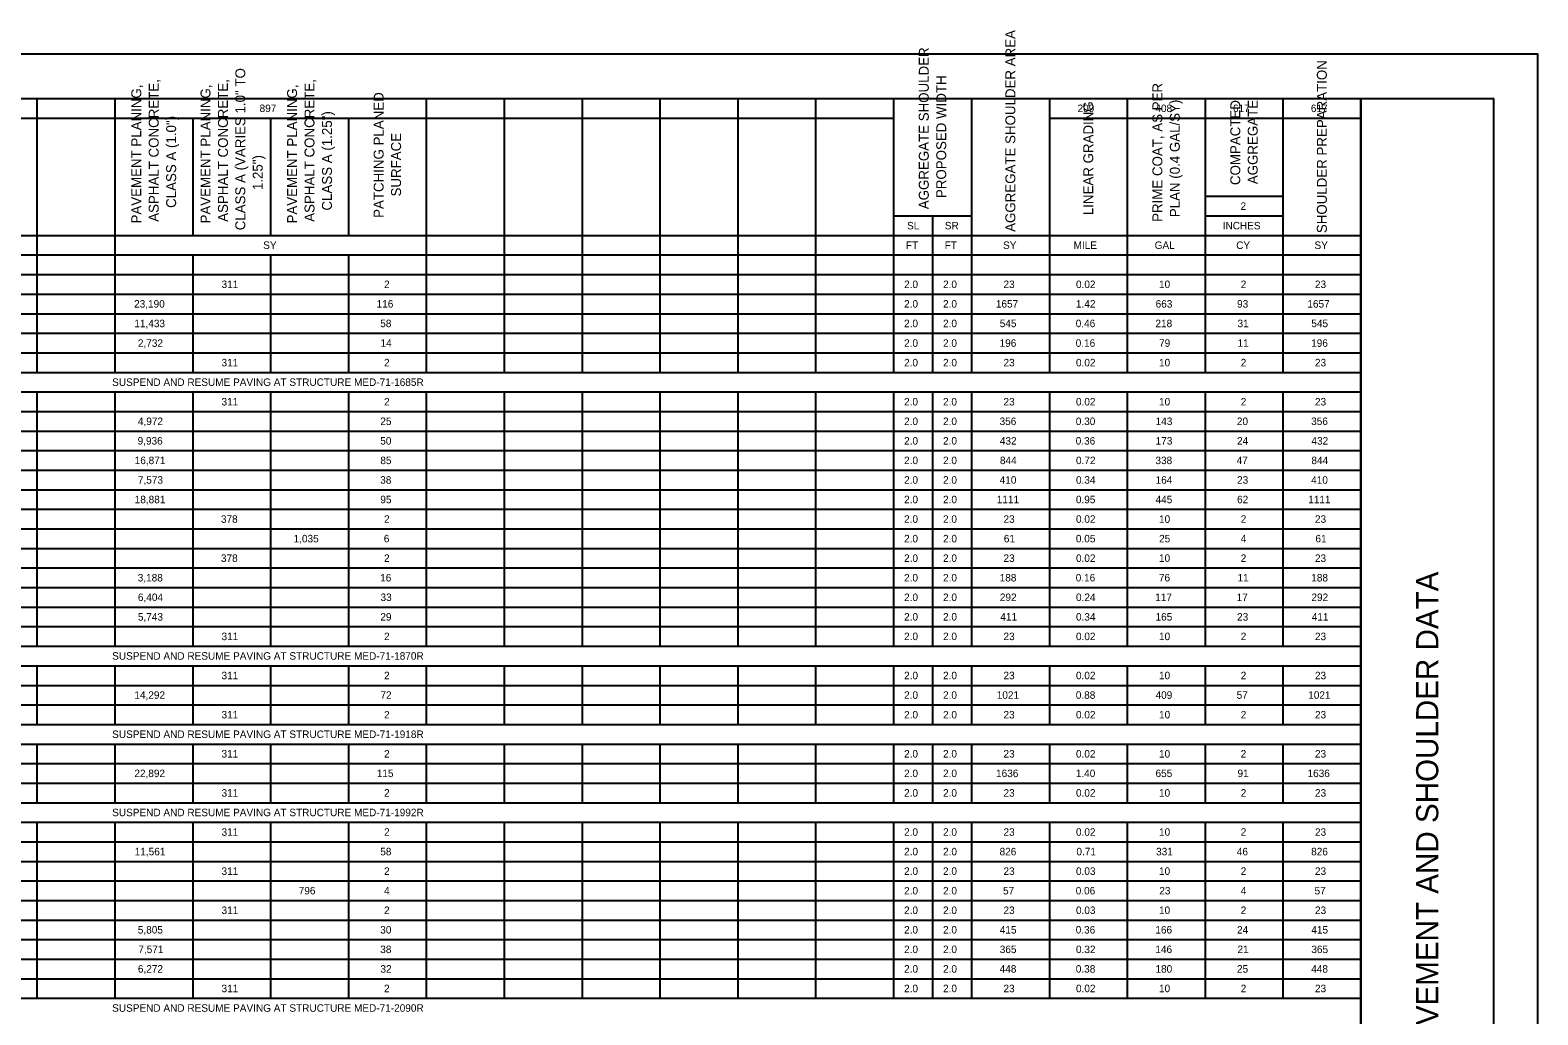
# Model space of a CAD drawing. Extents: x 0 to 34, y 0 to 22.3.
# Drawn here: x 16.97 to 34, y 11.14 to 22.27 of the extents above; entities that cross this region are included whole.
import ezdxf

# ---------------------------------------------------------------- set-up
doc = ezdxf.new("R2010")
doc.units = 0
for name, color, linetype in [('SH_Border', 7, 'Continuous'), ('SH_Cut_Line', 7, 'Continuous'), ('SH_Data', 7, 'Continuous'), ('SH_Text', 7, 'Continuous')]:
    doc.layers.add(name, color=color, linetype=linetype)

msp = doc.modelspace()

# ---------------------------------------------------------------- linework, layer by layer
at = {"layer": 'SH_Border'}
msp.add_line((32, 0.5), (32, 21.5), dxfattribs=at)
msp.add_lwpolyline([(1.5, 21.5), (33.5, 21.5), (33.5, 0.5), (1.5, 0.5)], close=True, dxfattribs=at)
at = {"layer": 'SH_Cut_Line'}
msp.add_lwpolyline([(0, 0), (34, 0), (34, 22), (0, 22)], close=True, dxfattribs=at)
at = {"layer": 'SH_Text'}
for p, q in [((1.5, 21.5), (32, 21.5)), ((17.043, 21.5), (17.043, 18.405)), ((17.923, 21.5), (17.923, 18.405)), ((21.442, 21.5), (21.442, 18.405)), ((22.322, 21.5), (22.322, 18.405)), ((23.202, 21.5), (23.202, 18.405)), ((24.082, 21.5), (24.082, 18.405)), ((24.962, 21.5), (24.962, 18.405)), ((25.841, 21.5), (25.841, 18.405)), ((26.721, 21.5), (26.721, 18.405)), ((27.601, 21.5), (27.601, 18.405)), ((28.481, 21.5), (28.481, 18.405)), ((29.361, 21.5), (29.361, 18.405)), ((30.24, 21.5), (30.24, 18.405)), ((31.12, 21.5), (31.12, 18.405)), ((32, 21.5), (32, 0.5)), ((10.885, 21.279), (26.721, 21.279)), ((18.803, 21.279), (18.803, 19.953)), ((19.683, 21.279), (19.683, 19.953)), ((20.562, 21.279), (20.562, 19.953)), ((28.481, 21.279), (32, 21.279)), ((30.24, 20.395), (31.12, 20.395)), ((26.721, 20.174), (27.601, 20.174)), ((27.161, 20.174), (27.161, 18.405)), ((30.24, 20.174), (31.12, 20.174)), ((10.005, 19.953), (32, 19.953)), ((1.5, 19.732), (32, 19.732)), ((18.803, 19.732), (18.803, 18.405)), ((19.683, 19.732), (19.683, 18.405)), ((20.562, 19.732), (20.562, 18.405)), ((1.5, 19.511), (32, 19.511)), ((1.5, 19.289), (32, 19.289)), ((1.5, 19.068), (32, 19.068)), ((1.5, 18.847), (32, 18.847)), ((1.5, 18.626), (32, 18.626)), ((1.5, 18.405), (32, 18.405)), ((1.5, 18.184), (32, 18.184)), ((17.043, 18.184), (17.043, 15.311)), ((17.923, 18.184), (17.923, 15.311)), ((18.803, 18.184), (18.803, 15.311)), ((19.683, 18.184), (19.683, 15.311)), ((20.562, 18.184), (20.562, 15.311)), ((21.442, 18.184), (21.442, 15.311)), ((22.322, 18.184), (22.322, 15.311)), ((23.202, 18.184), (23.202, 15.311)), ((24.082, 18.184), (24.082, 15.311)), ((24.962, 18.184), (24.962, 15.311)), ((25.841, 18.184), (25.841, 15.311)), ((26.721, 18.184), (26.721, 15.311)), ((27.161, 18.184), (27.161, 15.311)), ((27.601, 18.184), (27.601, 15.311)), ((28.481, 18.184), (28.481, 15.311)), ((29.361, 18.184), (29.361, 15.311)), ((30.24, 18.184), (30.24, 15.311)), ((31.12, 18.184), (31.12, 15.311)), ((1.5, 17.963), (32, 17.963)), ((1.5, 17.742), (32, 17.742)), ((1.5, 17.521), (32, 17.521)), ((1.5, 17.3), (32, 17.3)), ((1.5, 17.079), (32, 17.079)), ((1.5, 16.858), (32, 16.858)), ((1.5, 16.637), (32, 16.637)), ((1.5, 16.416), (32, 16.416)), ((1.5, 16.195), (32, 16.195)), ((1.5, 15.974), (32, 15.974)), ((1.5, 15.753), (32, 15.753)), ((1.5, 15.532), (32, 15.532)), ((1.5, 15.311), (32, 15.311)), ((1.5, 15.089), (32, 15.089)), ((17.043, 15.089), (17.043, 14.426)), ((17.923, 15.089), (17.923, 14.426)), ((18.803, 15.089), (18.803, 14.426)), ((19.683, 15.089), (19.683, 14.426)), ((20.562, 15.089), (20.562, 14.426)), ((21.442, 15.089), (21.442, 14.426)), ((22.322, 15.089), (22.322, 14.426)), ((23.202, 15.089), (23.202, 14.426)), ((24.082, 15.089), (24.082, 14.426)), ((24.962, 15.089), (24.962, 14.426)), ((25.841, 15.089), (25.841, 14.426)), ((26.721, 15.089), (26.721, 14.426)), ((27.161, 15.089), (27.161, 14.426)), ((27.601, 15.089), (27.601, 14.426)), ((28.481, 15.089), (28.481, 14.426)), ((29.361, 15.089), (29.361, 14.426)), ((30.24, 15.089), (30.24, 14.426)), ((31.12, 15.089), (31.12, 14.426)), ((1.5, 14.868), (32, 14.868)), ((1.5, 14.647), (32, 14.647)), ((1.5, 14.426), (32, 14.426)), ((1.5, 14.205), (32, 14.205)), ((17.043, 14.205), (17.043, 13.542)), ((17.923, 14.205), (17.923, 13.542)), ((18.803, 14.205), (18.803, 13.542)), ((19.683, 14.205), (19.683, 13.542)), ((20.562, 14.205), (20.562, 13.542)), ((21.442, 14.205), (21.442, 13.542)), ((22.322, 14.205), (22.322, 13.542)), ((23.202, 14.205), (23.202, 13.542)), ((24.082, 14.205), (24.082, 13.542)), ((24.962, 14.205), (24.962, 13.542)), ((25.841, 14.205), (25.841, 13.542)), ((26.721, 14.205), (26.721, 13.542)), ((27.161, 14.205), (27.161, 13.542)), ((27.601, 14.205), (27.601, 13.542)), ((28.481, 14.205), (28.481, 13.542)), ((29.361, 14.205), (29.361, 13.542)), ((30.24, 14.205), (30.24, 13.542)), ((31.12, 14.205), (31.12, 13.542)), ((1.5, 13.984), (32, 13.984)), ((1.5, 13.763), (32, 13.763)), ((1.5, 13.542), (32, 13.542)), ((1.5, 13.321), (32, 13.321)), ((17.043, 13.321), (17.043, 11.332)), ((17.923, 13.321), (17.923, 11.332)), ((18.803, 13.321), (18.803, 11.332)), ((19.683, 13.321), (19.683, 11.332)), ((20.562, 13.321), (20.562, 11.332)), ((21.442, 13.321), (21.442, 11.332)), ((22.322, 13.321), (22.322, 11.332)), ((23.202, 13.321), (23.202, 11.332)), ((24.082, 13.321), (24.082, 11.332)), ((24.962, 13.321), (24.962, 11.332)), ((25.841, 13.321), (25.841, 11.332)), ((26.721, 13.321), (26.721, 11.332)), ((27.161, 13.321), (27.161, 11.332)), ((27.601, 13.321), (27.601, 11.332)), ((28.481, 13.321), (28.481, 11.332)), ((29.361, 13.321), (29.361, 11.332)), ((30.24, 13.321), (30.24, 11.332)), ((31.12, 13.321), (31.12, 11.332)), ((1.5, 13.1), (32, 13.1)), ((1.5, 12.879), (32, 12.879)), ((1.5, 12.658), (32, 12.658)), ((1.5, 12.437), (32, 12.437)), ((1.5, 12.216), (32, 12.216)), ((1.5, 11.995), (32, 11.995)), ((1.5, 11.774), (32, 11.774)), ((1.5, 11.553), (32, 11.553)), ((1.5, 11.332), (32, 11.332))]:
    msp.add_line(p, q, dxfattribs=at)

# ---------------------------------------------------------------- texts
at = {"layer": 'SH_Data'}
msp.add_text('PAVEMENT AND SHOULDER DATA', height=0.25, rotation=90, dxfattribs=at).set_placement((32.875, 10.581))
at = {"layer": 'SH_Text'}
for s, height, p in [('AGGREGATE SHOULDER AREA', 0.11242, (28.097, 19.993)), ('AGGREGATE SHOULDER ', 0.11242, (27.119, 20.249)), ('CLASS A (VARIES 1.0" TO ', 0.11242, (19.397, 20.011)), ('SHOULDER PREPARATION', 0.11242, (31.616, 19.979)), ('PAVEMENT PLANING, ', 0.11242, (18.222, 20.088)), ('ASPHALT CONCRETE, ', 0.11242, (18.419, 20.107)), ('PAVEMENT PLANING, ', 0.11242, (19.004, 20.088)), ('ASPHALT CONCRETE, ', 0.11242, (19.201, 20.107)), ('PAVEMENT PLANING, ', 0.11242, (19.982, 20.088)), ('ASPHALT CONCRETE, ', 0.11242, (20.179, 20.107)), ('PROPOSED WIDTH', 0.11242, (27.316, 20.375)), ('PRIME COAT, AS PER ', 0.11242, (29.758, 20.106)), ('PATCHING PLANED ', 0.11242, (20.96, 20.151)), ('PLAN (0.4 GAL/SY)', 0.11242, (29.955, 20.159)), ('COMPACTED ', 0.1124, (30.638, 20.522)), ('AGGREGATE', 0.1124, (30.835, 20.532)), ('CLASS A (1.0")', 0.11242, (18.616, 20.264)), ('CLASS A (1.25")', 0.11242, (20.376, 20.234)), ('LINEAR GRADING', 0.11242, (28.977, 20.182)), ('SURFACE', 0.1124, (21.157, 20.393)), ('1.25")', 0.1124, (19.594, 20.465))]:
    msp.add_text(s, height=height, rotation=90, dxfattribs=at).set_placement(p)
for s, height, p in [('897', 0.0847, (19.559, 21.347)), ('209', 0.0847, (28.8, 21.347)), ('408', 0.0847, (29.679, 21.347)), ('617', 0.0847, (30.556, 21.347)), ('617', 0.0847, (31.436, 21.347)), ('2', 0.0847, (30.641, 20.242)), ('SL', 0.0847, (26.873, 20.021)), ('SR', 0.0847, (27.3, 20.021)), ('INCHES', 0.0847, (30.44, 20.021)), ('SY', 0.0847, (19.6, 19.8)), ('FT', 0.0847, (26.86, 19.8)), ('FT', 0.0847, (27.299, 19.8)), ('SY', 0.0847, (27.958, 19.8)), ('MILE', 0.0847, (28.755, 19.8)), ('GAL', 0.0847, (29.671, 19.8)), ('CY', 0.0847, (30.592, 19.8)), ('SY', 0.0847, (31.477, 19.8)), ('311', 0.0847, (19.129, 19.358)), ('2', 0.0847, (20.965, 19.358)), ('2.0', 0.0847, (26.84, 19.358)), ('2.0', 0.0847, (27.28, 19.358)), ('23', 0.0847, (27.963, 19.358)), ('0.02', 0.0847, (28.782, 19.358)), ('10', 0.0847, (29.72, 19.358)), ('2', 0.0847, (30.643, 19.358)), ('23', 0.0847, (31.482, 19.358)), ('23,190', 0.0847, (18.141, 19.137)), ('116', 0.0847, (20.881, 19.137)), ('2.0', 0.0847, (26.84, 19.137)), ('2.0', 0.0847, (27.28, 19.137)), ('1657', 0.0847, (27.877, 19.137)), ('1.42', 0.0847, (28.782, 19.137)), ('663', 0.0847, (29.682, 19.137)), ('93', 0.0847, (30.602, 19.137)), ('1657', 0.0847, (31.396, 19.137)), ('11,433', 0.0847, (18.144, 18.916)), ('58', 0.0847, (20.922, 18.916)), ('2.0', 0.0847, (26.84, 18.916)), ('2.0', 0.0847, (27.28, 18.916)), ('545', 0.0847, (27.921, 18.916)), ('0.46', 0.0847, (28.779, 18.916)), ('218', 0.0847, (29.68, 18.916)), ('31', 0.0847, (30.607, 18.916)), ('545', 0.0847, (31.441, 18.916)), ('2,732', 0.0847, (18.184, 18.694)), ('14', 0.0847, (20.925, 18.694)), ('2.0', 0.0847, (26.84, 18.694)), ('2.0', 0.0847, (27.28, 18.694)), ('196', 0.0847, (27.919, 18.694)), ('0.16', 0.0847, (28.779, 18.694)), ('79', 0.0847, (29.721, 18.694)), ('11', 0.0847, (30.607, 18.694)), ('196', 0.0847, (31.439, 18.694)), ('311', 0.0847, (19.129, 18.473)), ('2', 0.0847, (20.965, 18.473)), ('2.0', 0.0847, (26.84, 18.473)), ('2.0', 0.0847, (27.28, 18.473)), ('23', 0.0847, (27.963, 18.473)), ('0.02', 0.0847, (28.782, 18.473)), ('10', 0.0847, (29.72, 18.473)), ('2', 0.0847, (30.643, 18.473)), ('23', 0.0847, (31.482, 18.473)), ('SUSPEND AND RESUME PAVING AT STRUCTURE MED-71-1685R', 0.08474, (17.893, 18.252)), ('311', 0.0847, (19.129, 18.031)), ('2', 0.0847, (20.965, 18.031)), ('2.0', 0.0847, (26.84, 18.031)), ('2.0', 0.0847, (27.28, 18.031)), ('23', 0.0847, (27.963, 18.031)), ('0.02', 0.0847, (28.782, 18.031)), ('10', 0.0847, (29.72, 18.031)), ('2', 0.0847, (30.643, 18.031)), ('23', 0.0847, (31.482, 18.031)), ('4,972', 0.0847, (18.184, 17.81)), ('25', 0.0847, (20.923, 17.81)), ('2.0', 0.0847, (26.84, 17.81)), ('2.0', 0.0847, (27.28, 17.81)), ('356', 0.0847, (27.919, 17.81)), ('0.30', 0.0847, (28.78, 17.81)), ('143', 0.0847, (29.682, 17.81)), ('20', 0.0847, (30.6, 17.81)), ('356', 0.0847, (31.439, 17.81)), ('9,936', 0.0847, (18.181, 17.589)), ('50', 0.0847, (20.922, 17.589)), ('2.0', 0.0847, (26.84, 17.589)), ('2.0', 0.0847, (27.28, 17.589)), ('432', 0.0847, (27.922, 17.589)), ('0.36', 0.0847, (28.779, 17.589)), ('173', 0.0847, (29.682, 17.589)), ('24', 0.0847, (30.602, 17.589)), ('432', 0.0847, (31.442, 17.589)), ('16,871', 0.0847, (18.148, 17.368)), ('85', 0.0847, (20.923, 17.368)), ('2.0', 0.0847, (26.84, 17.368)), ('2.0', 0.0847, (27.28, 17.368)), ('844', 0.0847, (27.923, 17.368)), ('0.72', 0.0847, (28.782, 17.368)), ('338', 0.0847, (29.68, 17.368)), ('47', 0.0847, (30.597, 17.368)), ('844', 0.0847, (31.442, 17.368)), ('7,573', 0.0847, (18.184, 17.147)), ('38', 0.0847, (20.922, 17.147)), ('2.0', 0.0847, (26.84, 17.147)), ('2.0', 0.0847, (27.28, 17.147)), ('410', 0.0847, (27.92, 17.147)), ('0.34', 0.0847, (28.782, 17.147)), ('164', 0.0847, (29.682, 17.147)), ('23', 0.0847, (30.602, 17.147)), ('410', 0.0847, (31.439, 17.147)), ('18,881', 0.0847, (18.148, 16.926)), ('95', 0.0847, (20.923, 16.926)), ('2.0', 0.0847, (26.84, 16.926)), ('2.0', 0.0847, (27.28, 16.926)), ('1111', 0.0847, (27.887, 16.926)), ('0.95', 0.0847, (28.781, 16.926)), ('445', 0.0847, (29.681, 16.926)), ('62', 0.0847, (30.602, 16.926)), ('1111', 0.0847, (31.406, 16.926)), ('378', 0.0847, (19.122, 16.705)), ('2', 0.0847, (20.965, 16.705)), ('2.0', 0.0847, (26.84, 16.705)), ('2.0', 0.0847, (27.28, 16.705)), ('23', 0.0847, (27.963, 16.705)), ('0.02', 0.0847, (28.782, 16.705)), ('10', 0.0847, (29.72, 16.705)), ('2', 0.0847, (30.643, 16.705)), ('23', 0.0847, (31.482, 16.705)), ('1,035', 0.0847, (19.943, 16.484)), ('6', 0.0847, (20.962, 16.484)), ('2.0', 0.0847, (26.84, 16.484)), ('2.0', 0.0847, (27.28, 16.484)), ('61', 0.0847, (27.967, 16.484)), ('0.05', 0.0847, (28.781, 16.484)), ('25', 0.0847, (29.721, 16.484)), ('4', 0.0847, (30.643, 16.484)), ('61', 0.0847, (31.487, 16.484)), ('378', 0.0847, (19.122, 16.263)), ('2', 0.0847, (20.965, 16.263)), ('2.0', 0.0847, (26.84, 16.263)), ('2.0', 0.0847, (27.28, 16.263)), ('23', 0.0847, (27.963, 16.263)), ('0.02', 0.0847, (28.782, 16.263)), ('10', 0.0847, (29.72, 16.263)), ('2', 0.0847, (30.643, 16.263)), ('23', 0.0847, (31.482, 16.263)), ('3,188', 0.0847, (18.182, 16.042)), ('16', 0.0847, (20.921, 16.042)), ('2.0', 0.0847, (26.84, 16.042)), ('2.0', 0.0847, (27.28, 16.042)), ('188', 0.0847, (27.92, 16.042)), ('0.16', 0.0847, (28.779, 16.042)), ('76', 0.0847, (29.719, 16.042)), ('11', 0.0847, (30.607, 16.042)), ('188', 0.0847, (31.44, 16.042)), ('6,404', 0.0847, (18.184, 15.821)), ('33', 0.0847, (20.925, 15.821)), ('2.0', 0.0847, (26.84, 15.821)), ('2.0', 0.0847, (27.28, 15.821)), ('292', 0.0847, (27.922, 15.821)), ('0.24', 0.0847, (28.782, 15.821)), ('117', 0.0847, (29.677, 15.821)), ('17', 0.0847, (30.597, 15.821)), ('292', 0.0847, (31.442, 15.821)), ('5,743', 0.0847, (18.184, 15.6)), ('29', 0.0847, (20.923, 15.6)), ('2.0', 0.0847, (26.84, 15.6)), ('2.0', 0.0847, (27.28, 15.6)), ('411', 0.0847, (27.927, 15.6)), ('0.34', 0.0847, (28.782, 15.6)), ('165', 0.0847, (29.681, 15.6)), ('23', 0.0847, (30.602, 15.6)), ('411', 0.0847, (31.446, 15.6)), ('311', 0.0847, (19.129, 15.379)), ('2', 0.0847, (20.965, 15.379)), ('2.0', 0.0847, (26.84, 15.379)), ('2.0', 0.0847, (27.28, 15.379)), ('23', 0.0847, (27.963, 15.379)), ('0.02', 0.0847, (28.782, 15.379)), ('10', 0.0847, (29.72, 15.379)), ('2', 0.0847, (30.643, 15.379)), ('23', 0.0847, (31.482, 15.379)), ('SUSPEND AND RESUME PAVING AT STRUCTURE MED-71-1870R', 0.08474, (17.893, 15.158)), ('311', 0.0847, (19.129, 14.937)), ('2', 0.0847, (20.965, 14.937)), ('2.0', 0.0847, (26.84, 14.937)), ('2.0', 0.0847, (27.28, 14.937)), ('23', 0.0847, (27.963, 14.937)), ('0.02', 0.0847, (28.782, 14.937)), ('10', 0.0847, (29.72, 14.937)), ('2', 0.0847, (30.643, 14.937)), ('23', 0.0847, (31.482, 14.937)), ('14,292', 0.0847, (18.144, 14.716)), ('72', 0.0847, (20.924, 14.716)), ('2.0', 0.0847, (26.84, 14.716)), ('2.0', 0.0847, (27.28, 14.716)), ('1021', 0.0847, (27.887, 14.716)), ('0.88', 0.0847, (28.78, 14.716)), ('409', 0.0847, (29.681, 14.716)), ('57', 0.0847, (30.597, 14.716)), ('1021', 0.0847, (31.406, 14.716)), ('311', 0.0847, (19.129, 14.494)), ('2', 0.0847, (20.965, 14.494)), ('2.0', 0.0847, (26.84, 14.494)), ('2.0', 0.0847, (27.28, 14.494)), ('23', 0.0847, (27.963, 14.494)), ('0.02', 0.0847, (28.782, 14.494)), ('10', 0.0847, (29.72, 14.494)), ('2', 0.0847, (30.643, 14.494)), ('23', 0.0847, (31.482, 14.494)), ('SUSPEND AND RESUME PAVING AT STRUCTURE MED-71-1918R', 0.08474, (17.893, 14.273)), ('311', 0.0847, (19.129, 14.052)), ('2', 0.0847, (20.965, 14.052)), ('2.0', 0.0847, (26.84, 14.052)), ('2.0', 0.0847, (27.28, 14.052)), ('23', 0.0847, (27.963, 14.052)), ('0.02', 0.0847, (28.782, 14.052)), ('10', 0.0847, (29.72, 14.052)), ('2', 0.0847, (30.643, 14.052)), ('23', 0.0847, (31.482, 14.052)), ('22,892', 0.0847, (18.144, 13.831)), ('115', 0.0847, (20.883, 13.831)), ('2.0', 0.0847, (26.84, 13.831)), ('2.0', 0.0847, (27.28, 13.831)), ('1636', 0.0847, (27.879, 13.831)), ('1.40', 0.0847, (28.78, 13.831)), ('655', 0.0847, (29.681, 13.831)), ('91', 0.0847, (30.607, 13.831)), ('1636', 0.0847, (31.398, 13.831)), ('311', 0.0847, (19.129, 13.61)), ('2', 0.0847, (20.965, 13.61)), ('2.0', 0.0847, (26.84, 13.61)), ('2.0', 0.0847, (27.28, 13.61)), ('23', 0.0847, (27.963, 13.61)), ('0.02', 0.0847, (28.782, 13.61)), ('10', 0.0847, (29.72, 13.61)), ('2', 0.0847, (30.643, 13.61)), ('23', 0.0847, (31.482, 13.61)), ('SUSPEND AND RESUME PAVING AT STRUCTURE MED-71-1992R', 0.08474, (17.893, 13.389)), ('311', 0.0847, (19.129, 13.168)), ('2', 0.0847, (20.965, 13.168)), ('2.0', 0.0847, (26.84, 13.168)), ('2.0', 0.0847, (27.28, 13.168)), ('23', 0.0847, (27.963, 13.168)), ('0.02', 0.0847, (28.782, 13.168)), ('10', 0.0847, (29.72, 13.168)), ('2', 0.0847, (30.643, 13.168)), ('23', 0.0847, (31.482, 13.168)), ('11,561', 0.0847, (18.148, 12.947)), ('58', 0.0847, (20.922, 12.947)), ('2.0', 0.0847, (26.84, 12.947)), ('2.0', 0.0847, (27.28, 12.947)), ('826', 0.0847, (27.919, 12.947)), ('0.71', 0.0847, (28.787, 12.947)), ('331', 0.0847, (29.687, 12.947)), ('46', 0.0847, (30.599, 12.947)), ('826', 0.0847, (31.439, 12.947)), ('311', 0.0847, (19.129, 12.726)), ('2', 0.0847, (20.965, 12.726)), ('2.0', 0.0847, (26.84, 12.726)), ('2.0', 0.0847, (27.28, 12.726)), ('23', 0.0847, (27.963, 12.726)), ('0.03', 0.0847, (28.782, 12.726)), ('10', 0.0847, (29.72, 12.726)), ('2', 0.0847, (30.643, 12.726)), ('23', 0.0847, (31.482, 12.726)), ('796', 0.0847, (20.001, 12.505)), ('4', 0.0847, (20.965, 12.505)), ('2.0', 0.0847, (26.84, 12.505)), ('2.0', 0.0847, (27.28, 12.505)), ('57', 0.0847, (27.958, 12.505)), ('0.06', 0.0847, (28.779, 12.505)), ('23', 0.0847, (29.723, 12.505)), ('4', 0.0847, (30.643, 12.505)), ('57', 0.0847, (31.477, 12.505)), ('311', 0.0847, (19.129, 12.284)), ('2', 0.0847, (20.965, 12.284)), ('2.0', 0.0847, (26.84, 12.284)), ('2.0', 0.0847, (27.28, 12.284)), ('23', 0.0847, (27.963, 12.284)), ('0.03', 0.0847, (28.782, 12.284)), ('10', 0.0847, (29.72, 12.284)), ('2', 0.0847, (30.643, 12.284)), ('23', 0.0847, (31.482, 12.284)), ('5,805', 0.0847, (18.183, 12.063)), ('30', 0.0847, (20.922, 12.063)), ('2.0', 0.0847, (26.84, 12.063)), ('2.0', 0.0847, (27.28, 12.063)), ('415', 0.0847, (27.921, 12.063)), ('0.36', 0.0847, (28.779, 12.063)), ('166', 0.0847, (29.679, 12.063)), ('24', 0.0847, (30.602, 12.063)), ('415', 0.0847, (31.441, 12.063)), ('7,571', 0.0847, (18.189, 11.842)), ('38', 0.0847, (20.922, 11.842)), ('2.0', 0.0847, (26.84, 11.842)), ('2.0', 0.0847, (27.28, 11.842)), ('365', 0.0847, (27.921, 11.842)), ('0.32', 0.0847, (28.782, 11.842)), ('146', 0.0847, (29.679, 11.842)), ('21', 0.0847, (30.607, 11.842)), ('365', 0.0847, (31.441, 11.842)), ('6,272', 0.0847, (18.184, 11.621)), ('32', 0.0847, (20.924, 11.621)), ('2.0', 0.0847, (26.84, 11.621)), ('2.0', 0.0847, (27.28, 11.621)), ('448', 0.0847, (27.92, 11.621)), ('0.38', 0.0847, (28.78, 11.621)), ('180', 0.0847, (29.68, 11.621)), ('25', 0.0847, (30.601, 11.621)), ('448', 0.0847, (31.44, 11.621)), ('311', 0.0847, (19.129, 11.4)), ('2', 0.0847, (20.965, 11.4)), ('2.0', 0.0847, (26.84, 11.4)), ('2.0', 0.0847, (27.28, 11.4)), ('23', 0.0847, (27.963, 11.4)), ('0.02', 0.0847, (28.782, 11.4)), ('10', 0.0847, (29.72, 11.4)), ('2', 0.0847, (30.643, 11.4)), ('23', 0.0847, (31.482, 11.4)), ('SUSPEND AND RESUME PAVING AT STRUCTURE MED-71-2090R', 0.08474, (17.893, 11.179))]:
    msp.add_text(s, height=height, dxfattribs=at).set_placement(p)

doc.saveas('drawing.dxf')
